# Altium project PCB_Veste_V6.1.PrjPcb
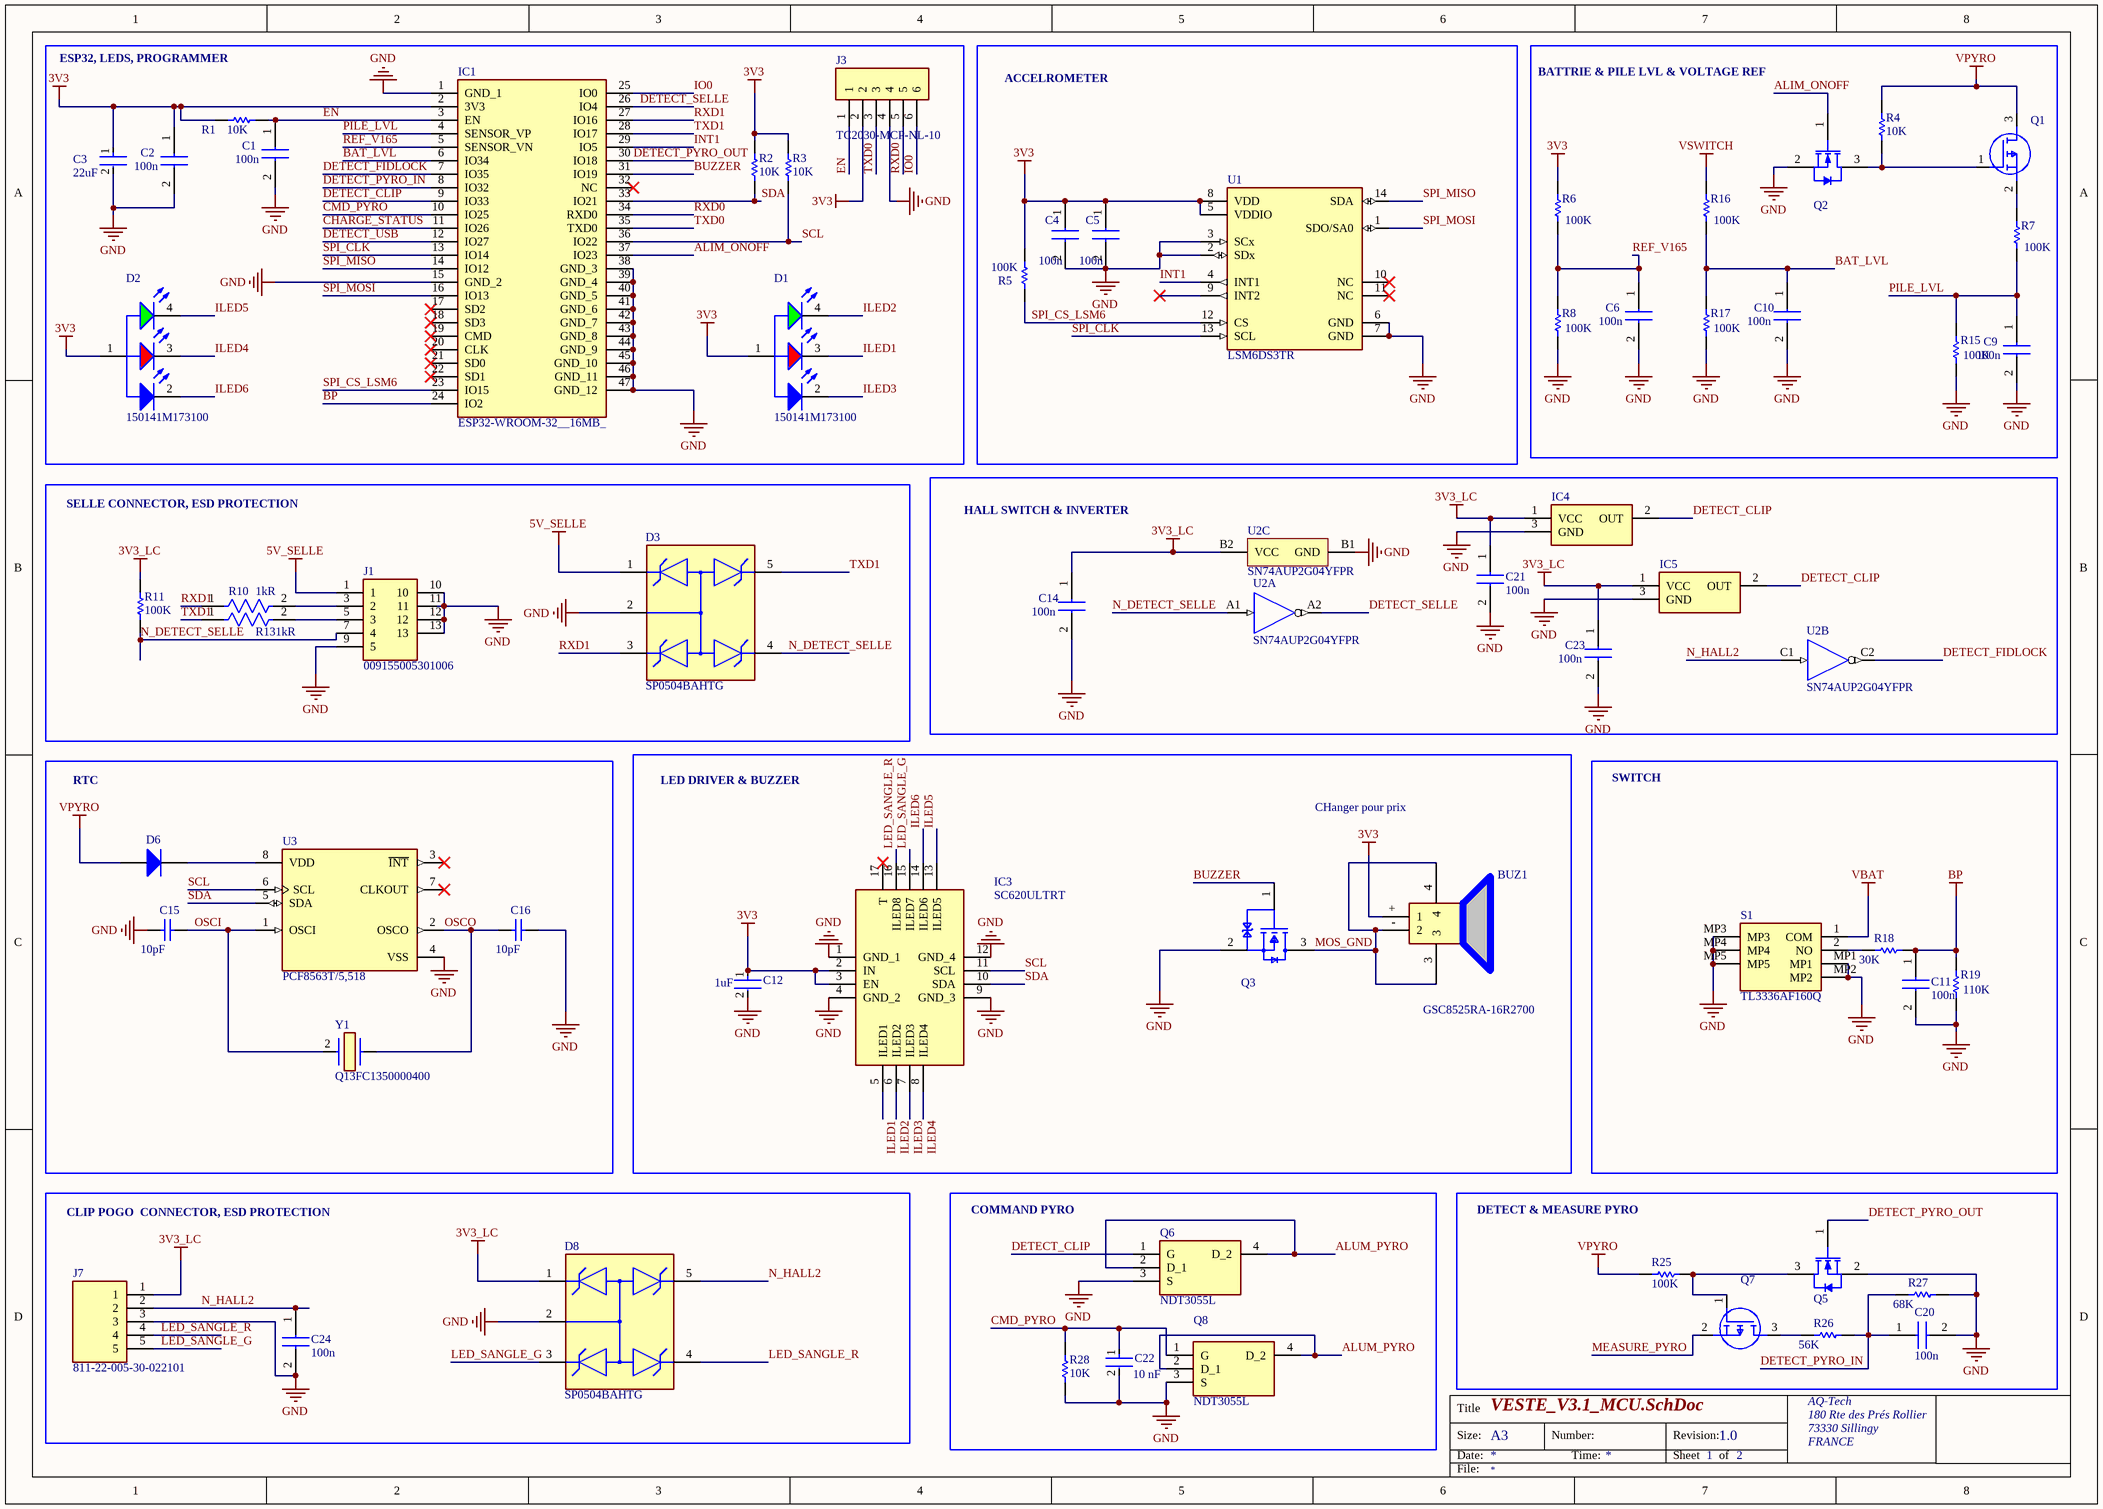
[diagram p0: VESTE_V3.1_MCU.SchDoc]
CAGE_CODE: ?????; CONTRACT_NUMBER: <CONTRACT NO>; DOC_NO_ASSY_DWG: <ASSY DWG NO>; DOC_NO_BOM: <BOM DOC NO>; DOC_NO_FAB_DWG: <FAB DWG NO>; DOC_NO_SCH_DWG: <SCH DWG NO>; PCB_2_DEC_TOL: +/-.01; PCB_3_DEC_TOL: +/-.010; PCB_ANG_TOL: +/-1/2; PCB_ASSEMBLY_NO: <PCB ASSY NO>; PCB_CHECKER: - -----; PCB_CHECKER_APP_DATE: --/--/----; PCB_DESIGNER: - -----; PCB_DESIGNER_APP_DATE: --/--/----; PCB_DWG_NO: <PCB DWG NO>; PCB_ENGINEER: - -----; PCB_ENGINEER_APP_DATE: --/--/----; PCB_PART_NUMBER: <PCB PN>; PCB_REV: A; SCH_REV: A
2 sheets, 108 parts. Net scope: global (net labels, ports and power ports of the same name join across sheets).
Board file: PCB_VESTE_6.1.PcbDoc
Sheets:
  VESTE_V3.1_MCU.SchDoc
  VESTE_V3.1_PSU.SchDoc

## Sheet VESTE_V3.1_MCU.SchDoc: DEV-09-17 MERE
size A3; ENG_APP_DATE: --/--/--; DSN_APP_DATE: --/--/--; CHK_APP_DATE: --/--/--; Date: 22/11/2017; Organization: Altium Limited; Address1: L3, 12a Rodborough Rd; Address2: Frenchs Forest; Address3: NSW; Address4: Australia 2086; Revision: 1.0; SheetNumber: 1; SheetTotal: 2; PageSetup: Record=PageOptions¦CenterHorizontal=True¦CenterVertical=True¦PrintScale=0.97¦XCorrection=1.00¦YCorrection=1.00¦PrintKind=0¦BorderSize=5000000¦LeftOffset=0¦BottomOffset=0¦Orientation=2¦PaperLength=1000¦PaperWidth=1000¦Scale=100¦PaperSource=7¦PrintQuality=-3¦MediaType=1¦DitherType=10¦PaperKind=A4¦PrintScaleMode=1

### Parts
BUZ1  GSC8525RA-16R2700  [BUZ-SMD_4P-L8.5-W8.5-P8.50-TL]
C1  Capacitance: 100n  [CAPC1608X90N]
C2  Capacitance: 100n  [CAPC1608X90N]
C3  Capacitance: 22uF  [FP-GRM188-0_2-IPC_C]  (hidden comment: GRM188R61A226ME15D)
C4  Capacitance: 100n  [CAPC1608X90N]
C5  Capacitance: 100n  [CAPC1608X90N]
C6  Capacitance: 100n  [CAPC1608X90N]
C9  Capacitance: 100n  [CAPC1608X90N]
C10  Capacitance: 100n  [CAPC1608X90N]
C11  Capacitance: 100n  [CAPC1608X90N]
C12  Capacitance: 1uF  [FP-CL511-IPC_C]  (hidden comment: CL05A105KP5NNNC)
C14  Capacitance: 100n  [CAPC1608X90N]
C15  Capacitance: 10pF  [CAPC1005X55X25ML05T05]  (hidden comment: CC0402JRNPO9BN100)
C16  Capacitance: 10pF  [CAPC1005X55X25ML05T05]  (hidden comment: CC0402JRNPO9BN100)
C20  Capacitance: 100n  [CAPC1608X90N]
C21  Capacitance: 100n  [CAPC1608X90N]
C22  value 10 nF  [FP-CC0402-MFG]  (hidden comment: CC0402KRX7R9BB103)
C23  Capacitance: 100n  [CAPC1608X90N]
C24  Capacitance: 100n  [CAPC1608X90N]
D1  150141M173100  [WL-SFTW_3528_150141M173100]
D2  150141M173100  [WL-SFTW_3528_150141M173100]
D3  SP0504BAHTG  [FP-SP0504BAHTG-MFG]
D6  1N4148WS-7-F  [DIOD-SOD323-2-A_V]  (value not drawn)
D8  SP0504BAHTG  [FP-SP0504BAHTG-MFG]
IC1  ESP32-WROOM-32__16MB_  [ESP32WROOM3216MB]
IC3  SC620ULTRT  [QFN50P300X300X60-17N]
IC4  TMAG5231A1CQDBZR  [SOT95P237X112-3N]  (value not drawn)
IC5  TMAG5231A1CQDBZR  [SOT95P237X112-3N]  (value not drawn)
J1  009155005301006  [009155005301006]
J3  TC2030-MCP-NL-10  [TC2030MCPNL10]
J7  811-22-005-30-022101  [8112200530022101]
Q1  DMP3125L-7  [SOT96P240X110-3N]  (value not drawn)
Q2  2N7002P,215  [NXP-SOT23_L]  (value not drawn)
Q3  DMN3730U-7  [FP-SOT23-MFG]  (value not drawn)
Q5  2N7002P,215  [NXP-SOT23_L]  (value not drawn)
Q6  NDT3055L  [SOT230P700X180-4N]
Q7  DMP3125L-7  [SOT96P240X110-3N]  (value not drawn)
Q8  NDT3055L  [SOT230P700X180-4N]
R1  Resistance: 10K  [RESC1005X40X25ML05T05]  (hidden comment: ERJ-2GEJ103X)
R2  Resistance: 10K  [RESC1005X40X25ML05T05]  (hidden comment: ERJ-2GEJ103X)
R3  Resistance: 10K  [RESC1005X40X25ML05T05]  (hidden comment: ERJ-2GEJ103X)
R4  Resistance: 10K  [RESC1005X40X25ML05T05]  (hidden comment: ERJ-2GEJ103X)
R5  Resistance: 100K  [RESC1005X40X25NL05T10]  (hidden comment: RC0402FR-07100KL)
R6  Resistance: 100K  [RESC1005X40X25NL05T10]  (hidden comment: RC0402FR-07100KL)
R7  Resistance: 100K  [RESC1005X40X25NL05T10]  (hidden comment: RC0402FR-07100KL)
R8  Resistance: 100K  [RESC1005X40X25NL05T10]  (hidden comment: RC0402FR-07100KL)
R10  Resistance: 1kR  [FP-RC0603-0_55-IPC_C]  (hidden comment: RC0603FR-071KL)
R11  Resistance: 100K  [RESC1005X40X25NL05T10]  (hidden comment: RC0402FR-07100KL)
R13  Resistance: 1kR  [FP-RC0603-0_55-IPC_C]  (hidden comment: RC0603FR-071KL)
R15  Resistance: 100K  [RESC1005X40X25NL05T10]  (hidden comment: RC0402FR-07100KL)
R16  Resistance: 100K  [RESC1005X40X25NL05T10]  (hidden comment: RC0402FR-07100KL)
R17  Resistance: 100K  [RESC1005X40X25NL05T10]  (hidden comment: RC0402FR-07100KL)
R18  Resistance: 30K  [RESC1005X40X25LL05T10]  (hidden comment: RC0402FR-0730KL)
R19  Resistance: 110K  [RESC1005X40X25LL05T10]  (hidden comment: RC0402FR-07110KL)
R25  Resistance: 100K  [RESC1005X40X25NL05T10]  (hidden comment: RC0402FR-07100KL)
R26  Resistance: 56K  [RESC1005X40X25ML05T10]  (hidden comment: RC0402FR-0756KL)
R27  Resistance: 68K  [RESC1005X40X25ML05T10]  (hidden comment: RC0402FR-0768KL)
R28  Resistance: 10K  [RESC1005X40X25ML05T05]  (hidden comment: ERJ-2GEJ103X)
S1  TL3336AF160Q  [TL3336AF160Q]
U1  LSM6DS3TR  [FP-LGA-14-DM00249496-MFG]
U2  SN74AUP2G04YFPR  [YFF0006AAAA]  (parts A,B,C of 3)
U3  PCF8563T/5,518  [FP-SOT96-1-MFG]
Y1  Q13FC1350000400  [Q13FC1350000400]

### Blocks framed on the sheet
ESP32, LEDS, PROGRAMMER: C1-C3 D1 D2 IC1 J3 R1-R3
ACCELROMETER: C4 C5 R5 U1
BATTRIE & PILE LVL & VOLTAGE REF: C6 C9 C10 Q1 Q2 R4 R6-R8 R15-R17
SELLE CONNECTOR, ESD PROTECTION: D3 J1 R10 R11 R13
HALL SWITCH & INVERTER: C14 C21 C23 IC4 IC5 U2
RTC: C15 C16 D6 U3 Y1
SWITCH: C11 R18 R19 S1
CLIP POGO  CONNECTOR, ESD PROTECTION: C24 D8 J7
COMMAND PYRO: C22 Q6 Q8 R28
DETECT & MEASURE PYRO: C20 Q5 Q7 R25-R27

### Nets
3V3: BUZ1.+(1) C2.1 C3.1 C4.1 C5.1 C12.1 D1.1(A) D2.1(A) IC1.2(3V3) IC3.2(IN) IC3.3(EN) J3.2 R1.2 R2.1 R3.1 R5.2 R6.2 U1.5(VDDIO) U1.8(VDD)
3V3_LC: C14.1 C21.1 C23.1 D8.1 IC4.1(VCC) IC5.1(VCC) J7.1 R11.1 U2.B2(VCC)
5V_SELLE: D3.1 J1.1
BP: C11.1 IC1.24(IO2) R18.2 R19.2
GND: C1.2 C2.2 C3.2 C4.2 C5.2 C6.2 C9.2 C10.2 C11.2 C12.2 C14.2 C15.1 C16.1 C20.2 C21.2 C22.2 C23.2 C24.2 D3.2 D8.2 IC1.1(GND_1) IC1.15(GND_2) IC1.38(GND_3) IC1.39(GND_4) IC1.40(GND_5) IC1.41(GND_6) IC1.42(GND_7) IC1.43(GND_8) IC1.44(GND_9) IC1.45(GND_10) IC1.46(GND_11) IC1.47(GND_12) IC3.1(GND_1) IC3.4(GND_2) IC3.9(GND_3) IC3.12(GND_4) IC4.3(GND) IC5.3(GND) J1.9(5) J1.10 J1.11 J1.12 J1.13 J3.4 J7.3 Q2.2(S) Q3.2(S) Q5.2(S) Q6.3(S) Q8.3(S) R8.1 R15.1 R17.1 R19.1 R27.2 R28.1 S1.MP1 S1.MP2 S1.MP3 S1.MP4 S1.MP5 U1.2(SDx) U1.3(SCx) U1.6(GND) U1.7(GND) U2.B1(GND) U3.4(VSS)
VBAT: S1.1(COM)
VPYRO: D6.1(A) Q1.3(D) R4.1 R25.2
VSWITCH: R16.2
ALIM_ONOFF: IC1.37(IO23) Q2.1(G)
ALUM_PYRO: Q6.2(D_1) Q6.4(D_2) Q7.2(S) Q8.2(D_1) Q8.4(D_2)  [also labelled MEASURE_PYRO]
BAT_LVL: C10.1 IC1.6(IO34) R16.1 R17.2
BUZZER: IC1.31(IO19) Q3.1(G)
CHARGE_STATUS: IC1.11(IO26)
CMD_PYRO: C22.1 IC1.10(IO25) Q8.1(G) R28.2
DETECT_CLIP: IC1.9(IO33) IC4.2(OUT) IC5.2(OUT) Q6.1(G)
DETECT_FIDLOCK: IC1.7(IO35) U2.C2(2Y)
DETECT_PYRO_IN: C20.1 IC1.8(IO32) R26.2 R27.1
DETECT_PYRO_OUT: IC1.30(IO18) Q5.1(G)
DETECT_SELLE: IC1.26(IO4) U2.A2(1Y)
DETECT_USB: IC1.12(IO27)
EN: C1.1 IC1.3(EN) J3.1 R1.1
ILED1: D1.3(K) IC3.5(ILED1)
ILED2: D1.4(K) IC3.6(ILED2)
ILED3: D1.2(K) IC3.7(ILED3)
ILED4: D2.3(K) IC3.8(ILED4)
ILED5: D2.4(K) IC3.13(ILED5)
ILED6: D2.2(K) IC3.14(ILED6)
INT1: IC1.29(IO5) U1.4(INT1)
IO0: IC1.25(IO0) J3.6
LED_SANGLE_G: D8.3 IC3.15(ILED7) J7.5
LED_SANGLE_R: D8.4 IC3.16(ILED8) J7.4
MOS_GND: BUZ1.3 BUZ1.4 BUZ1.-(2) Q3.3(D)
N_DETECT_SELLE: D3.4 J1.7(4) R11.2 U2.A1(1A)
N_HALL2: C24.1 D8.5 J7.2 U2.C1(2A)
OSCI: C15.2 U3.1(OSCI) Y1.2(CRYSTAL_2)
OSCO: C16.2 U3.2(OSCO) Y1.?1
PILE_LVL: C9.1 IC1.4(SENSOR_VP) R7.1 R15.2
REF_V165: C6.1 IC1.5(SENSOR_VN) R6.1 R8.2
RXD0: IC1.34(RXD0) J3.5
RXD1: D3.3 IC1.27(IO16) R10.1
SCL: IC1.36(IO22) IC3.11(SCL) R3.2 U3.6(SCL)
SDA: IC1.33(IO21) IC3.10(SDA) R2.2 U3.5(SDA)
SPI_CLK: IC1.13(IO14) U1.13(SCL)
SPI_CS_LSM6: IC1.23(IO15) R5.1 U1.12(CS)
SPI_MISO: IC1.14(IO12) U1.14(SDA)
SPI_MOSI: IC1.16(IO13) U1.1(SDO/SA0)
TXD0: IC1.35(TXD0) J3.3
TXD1: D3.5 IC1.28(IO17) R13.1
NetD6_2: D6.2(K) U3.8(VDD)
NetJ1_3: J1.3(2) R10.2
NetJ1_5: J1.5(3) R13.2
NetQ1_1: Q1.1(G) Q2.3(D) R4.2
NetQ1_2: Q1.2(S) R7.2
NetQ5_3: Q5.3(D) Q7.1(G) R25.1
NetQ7_3: Q7.3(D) R26.1
NetR18_1: R18.1 S1.2(NO)

Not connected (* = marked no-connect by the designer): IC1 17(SD2)* 18(SD3)* 19(CMD)* 20(CLK)* 21(SD0)* 22(SD1)* 32(NC)*; IC3 17(T)*; U1 9(INT2)* 10(NC)* 11(NC)*; U3 3(~{INT})* 7(CLKOUT)*

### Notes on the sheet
- LED DRIVER & BUZZER
- CHanger pour prix

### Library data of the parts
BUZ1 = GSC8525RA-16R2700: Externally Driven 88dB@3V,10cm Magnetic 3V 2.67kHz Plugin,L=8.5mm Buzzers ROHS
C1 C2 C4-C6 C9-C11 C14 C20 C21 C23 C24 = CL10B104KB8NNNC: Capacitor; Manufacturer_Name: SAMSUNG
C3 = CMP-2000-06337-3: Chip Multilayer Ceramic Capacitors for General Purpose, 0603, 22uF, X5R, 15%, 20%, 10V
C12 = CMP-13271-001936-1: Cap Ceramic 1uF 10V X5R ±10% SMD 0402 +85°C Paper T/R
C15 C16 = CMP-2100-03589-1: Chip Capacitor, 10 pF, +/- 5%, 50 V, -55 to 125 degC, 0402 (1005 Metric), RoHS, Tape and Reel; Manufacturer: Yageo; Insulation Resistance: 100GR; Voltage Rating (DC): 50V; Dielectric Material: Ceramic; Temperature Coefficient: 30ppm/degC; Dielectric: C0G
C22 = CMP-2100-03592-2: CAP CER 10000PF 50V X7R 0402; Manufacturer: YAGEO; Temperature Coefficient: 30ppm/°C; Material: Ceramic; Automotive Grade: NA; Tolerance: 0.1
D1 D2 = CMP-1431-00001-2: NexarPartId: 29717795; Forward Current: 100mA; Peak Wavelength: 465nm; Viewing Angle: 120°; Color: Green, Red; Max Reverse Voltage (DC): 5V; Forward Voltage: 3.2V; Dominant Wavelength: 520nm; Test Current: 20mA; Power Dissipation: 72mW; Wavelength: 470nm; Lens Style: Clear, Round; Luminous Intensity: 230mcd
D3 D8 = CMP-08607-000010-1: TVS DIODE 5.5V 8.5V SOT23-5; Manufacturer: Littelfuse; Direction: Unidirectional; Number Of Channels: 4; Value: 30pF; Standoff Height: 0mm
D6 = CMP-1667-00004-1: Fast Switching Diode, 75 V, 0.3 A, -65 to 150 degC, 2-Pin SOD323, RoHS, Tape and Reel
IC1 = ESP32-WROOM-32__16MB_: Integrated Circuit; Manufacturer_Name: Espressif Systems; Manufacturer_Part_Number: ESP32-WROOM-32 (16MB)
IC3 = SC620ULTRT: Integrated Circuit; Manufacturer_Name: SEMTECH
IC4 IC5 = TMAG5231A1CQDBZR: Integrated Circuit; Manufacturer_Name: Texas Instruments
J1 = 009155005301006: Connector; Manufacturer_Name: AVX; Manufacturer_Part_Number: 009155003301006
J3 = TC2030-MCP-NL-10: Connector; Manufacturer_Name: Tag Connect
J7 = 811-22-005-30-022101: Connector 5 pin Height  5,512 mm; Manufacturer_Name: Mill-Max
Q1 Q7 = DMP3125L-7: MOSFET (P-Channel); Manufacturer_Name: Diodes Inc.
Q2 Q5 = CMP-1259-00082-1: N-Channel Trench MOSFET, 60 V, 0.36 A, -55 to 150 degC, 3-Pin SOT23, Tape and Reel; Manufacturer: NXP Semiconductors; Channel Type: N; Automotive Qualified: Y; VDS [max] (V): 60; Packing: Tape & Reel; ID [max] (A): 0.36; VGSth [typ] (V): 1.75; IDM [max] (A): 1.2
Q3 = CMP-12801-000041-1: MOSFET N-CH 30V 750MA SOT23; Manufacturer: Diodes Inc.; Number Of N Channels: 1; Threshold Vgs Max: 0.95V; Max Junction Temp: +150°C; Automotive Grade: Grade 0; Gate To Source Voltage: 8V; Power Dissipation: 0.45W; Gate Charge At Vgs: 1.6nC @ 4.5V; Turn Off Delay Time: 38ns; Depletion Mode: False; Typ Forward Diode Voltage: 0.7V; Rthja Max: 275°C/W; Turn On Delay Time: 3.5ns; Drain To Source Resistance: 460mΩ; Pulse Drain Current: 10A; Threshold Vgs Min: 0.45V; Continuous Drain Current: 0.75A; Max Forward Diode Voltage: 1.2V; Standoff Height: 0.013mm; Input Capacitace At Vds: 64.3pF @ 25V
Q6 Q8 = NDT3055L: Transistor; Manufacturer_Name: onsemi
R1-R4 R28 = CMP-2002-00433-1: Manufacturer: Panasonic
R5-R8 R11 R15-R17 R25 = CMP-2002-07343-1: Manufacturer: Yageo / Phycomp
R10 R13 = CMP-1659-00009-5: RES 1K OHM 1% 1/10W 0603; Voltage Rating: 50V; Power Rating: 100mW; Temperature Coefficient: 100ppm/°C
R18 = CMP-2002-07602-1: Manufacturer: Yageo / Phycomp
R19 = CMP-2002-07022-1: Manufacturer: Yageo / Phycomp
R26 = CMP-1011-00708-2: Manufacturer: Yageo / Phycomp
R27 = CMP-1011-00717-2: Manufacturer: Yageo / Phycomp
S1 = TL3336AF160Q: Switch; Manufacturer_Name: E-Switch
U1 = CMP-2000-05193-2: IMU ACCEL/GYRO I2C/SPI 14VFLGA; Manufacturer: STMicroelectronics; Sensor Type: Temperature,Accelerometer,Gyroscope; Gyro Range: 125/250/500/1000/2000°/s; Min Supply Voltage: 1.62V; Operating Supply Current: 9-900uA; Accel Range: 2/4/8/16g; Max Supply Voltage: 3.6V; Sensor Output: I2C,SPI
U2 = CMP-0859-01053-4: Low-Power Dual Inverter Gate, YFP0006AAAA, LARGE T&R; Manufacturer: Texas Instruments; Logic: Inverting; Voltage(Nom)(V): 0.8,1.2,1.5,1.8,2.5,3.3; ICC @ Nom Voltage(Max)(mA): 0.0009; VCC(Max)(V): 3.6; Output Drive (IOL/IOH)(Max)(mA): 20/-20; tpd @ Nom Voltage(Max)(ns): 32.8,20.9,14.2,11,7.6,6.2; Input Type: CMOS; Schmitt Trigger: No; VCC(Min)(V): 0.8; Sub-Family: Inverting Buffer/Driver; Technology Family: AUP; Bits(#): 2; F @ Nom Voltage(Max)(Mhz): 100; Rating: Catalog
U3 = CMP-10083-000010-1: IC RTC CLK/CALENDAR I2C 8-SOIC; Manufacturer: NXP; Nominal Supply Current: 0.225-0.95uA; Interface: I2C,2-Wire; Min Supply Voltage: 1V; Frequency: 400kHz; Standoff Height: 0.1mm; Number Of Outputs: 1; Max Supply Voltage: 5.5V
Y1 = Q13FC1350000400: Crystal or Oscillator; Manufacturer_Name: Seiko Epson Corporation

## Sheet VESTE_V3.1_PSU.SchDoc: DEV-09-17 MERE
size A3; Date: 22/11/2017; Organization: Altium Limited; Address1: L3, 12a Rodborough Rd; Address2: Frenchs Forest; Address3: NSW; Address4: Australia 2086; Revision: 1.0; SheetNumber: 2; SheetTotal: 2; PageSetup: Record=PageOptions¦CenterHorizontal=True¦CenterVertical=True¦PrintScale=0.97¦XCorrection=1.00¦YCorrection=1.00¦PrintKind=0¦BorderSize=5000000¦LeftOffset=0¦BottomOffset=0¦Orientation=2¦PaperLength=1000¦PaperWidth=1000¦Scale=100¦PaperSource=7¦PrintQuality=-3¦MediaType=1¦DitherType=10¦PaperKind=A4¦PrintScaleMode=1
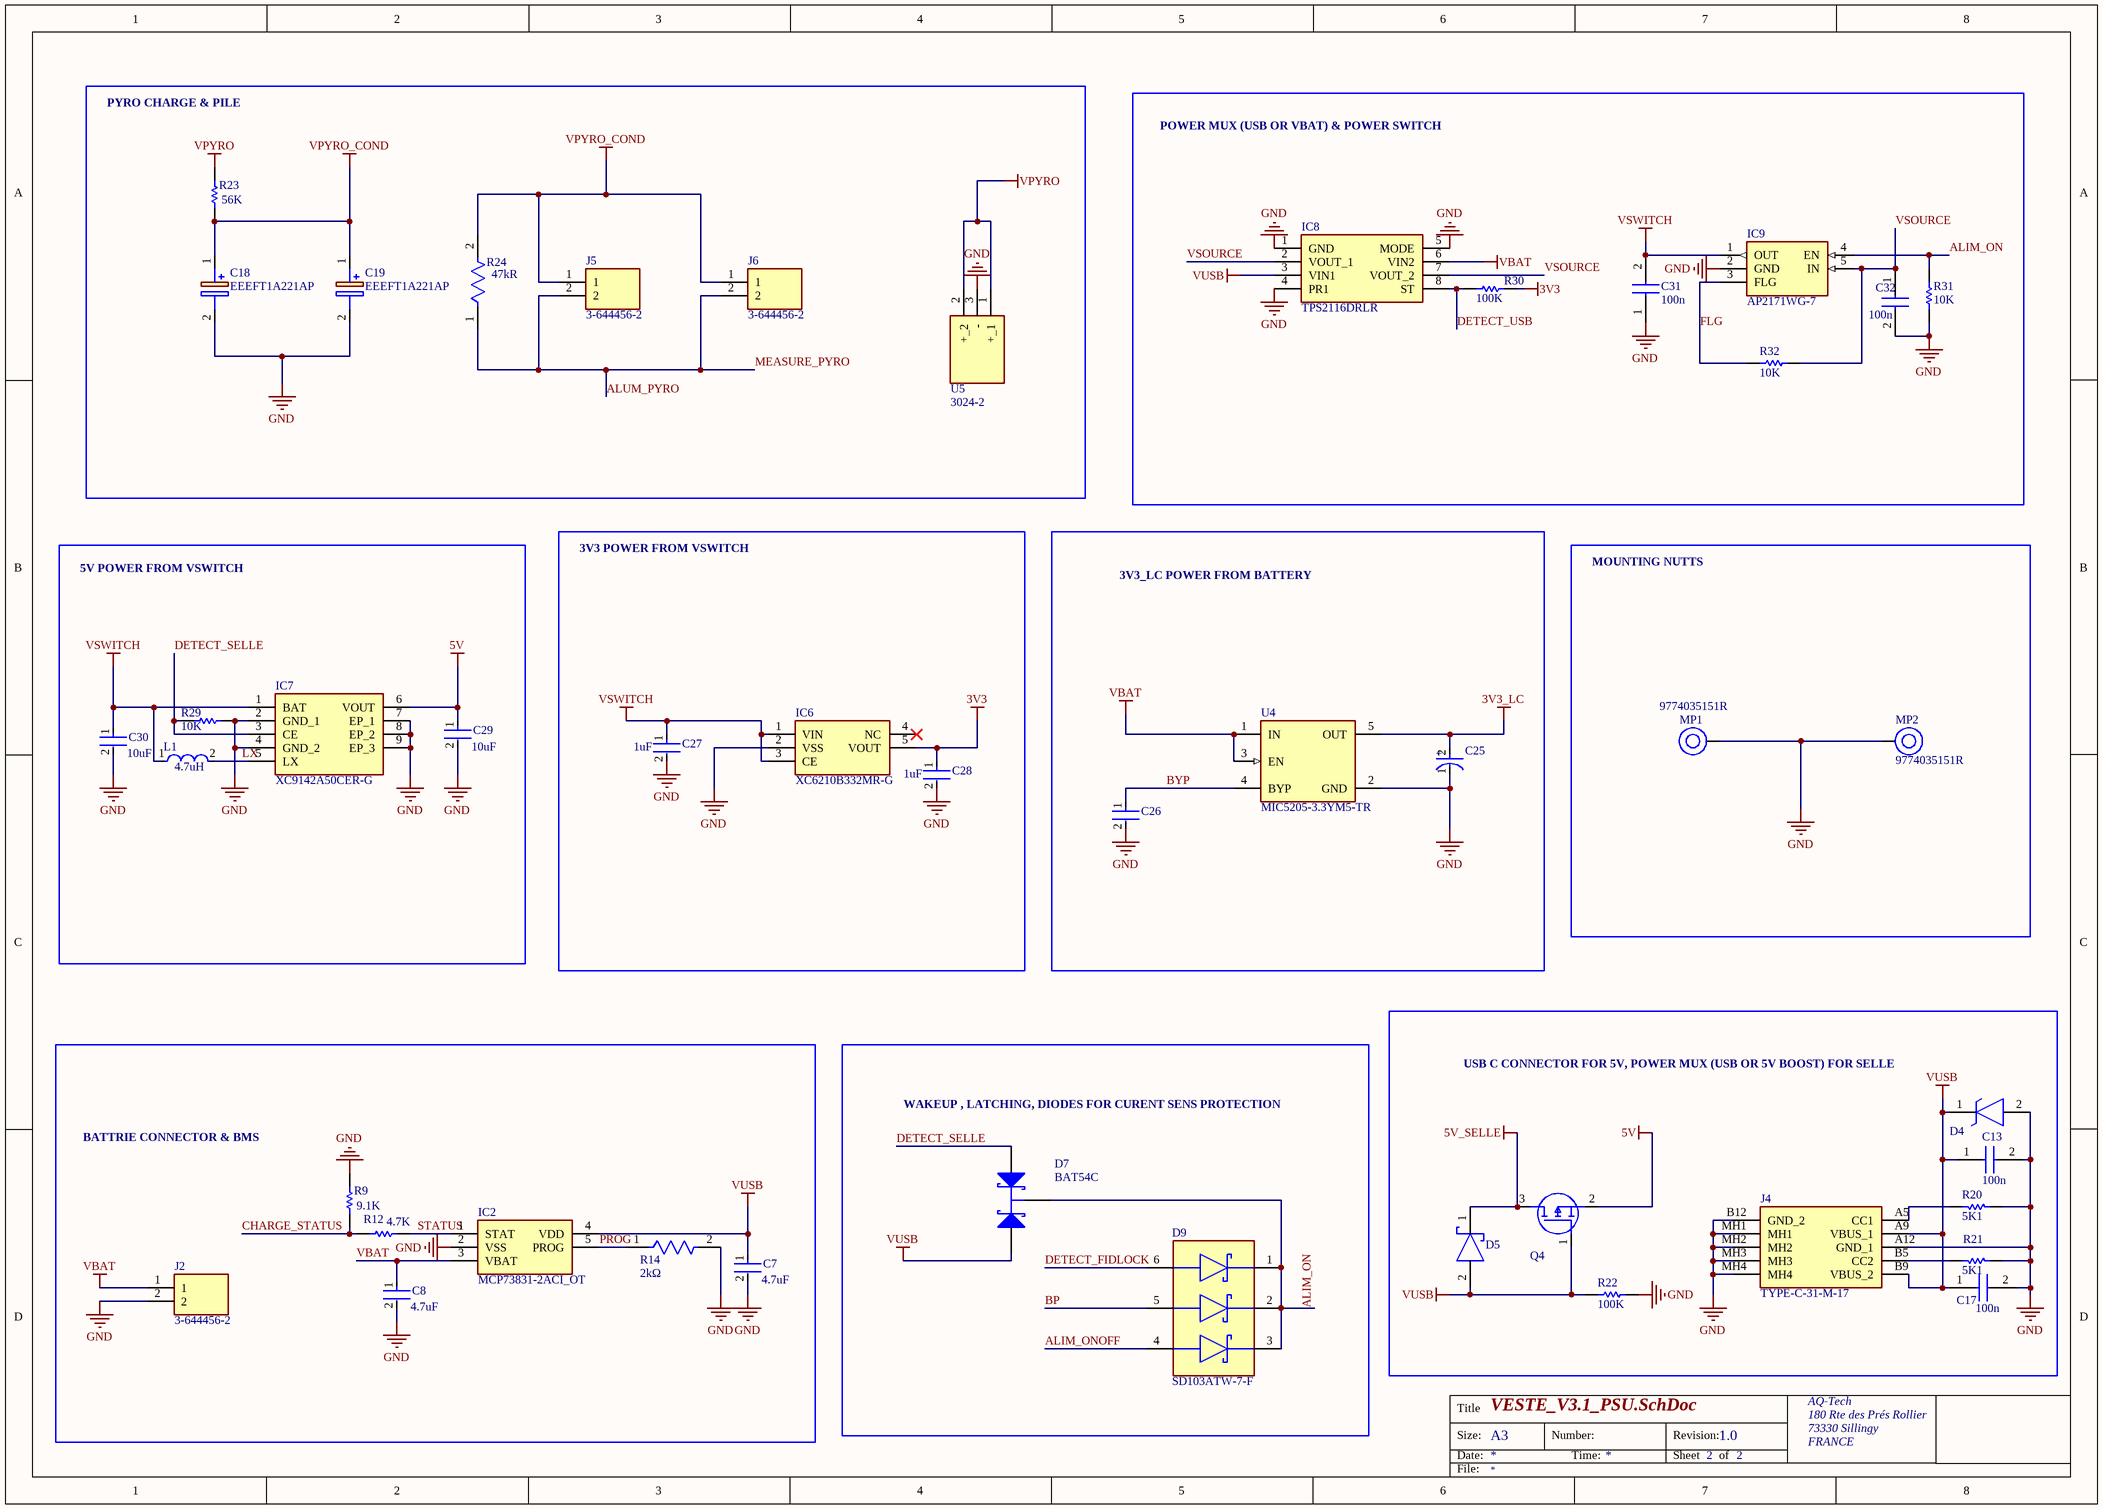
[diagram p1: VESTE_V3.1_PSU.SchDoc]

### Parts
C7  Capacitance: 4.7uF  [FP-CL828-IPC_C]  (hidden comment: CL05A475KP5NRNC)
C8  Capacitance: 4.7uF  [FP-CL828-IPC_C]  (hidden comment: CL05A475KP5NRNC)
C13  Capacitance: 100n  [CAPC1608X90N]
C17  Capacitance: 100n  [CAPC1608X90N]
C18  EEEFT1A221AP  [EEE1AA101SP]
C19  EEEFT1A221AP  [EEE1AA101SP]
C25  TAJA225K016RNJ  [FP-TAJA-MFG]  (value not drawn)
C26  CL05B471KB5NNNC  [FP-CL23-IPC_C]  (value not drawn)
C27  Capacitance: 1uF  [FP-CL511-IPC_C]  (hidden comment: CL05A105KP5NNNC)
C28  Capacitance: 1uF  [FP-CL511-IPC_C]  (hidden comment: CL05A105KP5NNNC)
C29  Capacitance: 10uF  [FP-CL05A106MP5NUNC-MFG]  (hidden comment: CL05A106MP5NUNC)
C30  Capacitance: 10uF  [FP-CL05A106MP5NUNC-MFG]  (hidden comment: CL05A106MP5NUNC)
C31  Capacitance: 100n  [CAPC1608X90N]
C32  Capacitance: 100n  [CAPC1608X90N]
D4  D5V0M1U2S9Q-7  [SODFL1006X40N]  (value not drawn)
D5  RB168MM100TR  [FP-PMDU-MFG]  (value not drawn)
D7  BAT54C  [NXP-SOT23-3_V]
D9  SD103ATW-7-F  [FP-SOT363-IPC_A]
IC2  MCP73831-2ACI_OT  [SOT95P270X145-5N]
IC6  XC6210B332MR-G  [SOT95P280X130-5N]
IC7  XC9142A50CER-G  [XC9142A50CERG]
IC8  TPS2116DRLR  [SOTFL50P160X60-8N]
IC9  AP2171WG-7  [SOT95P282X130-5N]
J2  3-644456-2  [HDRV2W67P0X254_1X2_478X234X1029P]
J4  TYPE-C-31-M-17  [TYPEC31M17]
J5  3-644456-2  [HDRV2W67P0X254_1X2_478X234X1029P]
J6  3-644456-2  [HDRV2W67P0X254_1X2_478X234X1029P]
L1  Inductance: 4.7uH  [FP-LQH5BPB_T0-MFG]  (hidden comment: LQH5BPN4R7NT0L)
MP1  9774035151R  [9774035151]
MP2  9774035151R  [9774035151]
Q4  DMP3125L-7  [SOT96P240X110-3N]  (value not drawn)
R9  Resistance: 9.1K  [RESC1005X40X25NL05T10]  (hidden comment: RC0402FR-079K1L)
R12  Resistance: 4.7K  [RESC1005X40X25NL05T10]  (hidden comment: RC0402FR-074K7L)
R14  Resistance: 2kΩ  [FP-RC_L0402-MFG]  (hidden comment: RC0402FR-072KL)
R20  Resistance: 5K1  [RESC1005X40X25NL05T10]  (hidden comment: RC0402FR-075K1L)
R21  Resistance: 5K1  [RESC1005X40X25NL05T10]  (hidden comment: RC0402FR-075K1L)
R22  Resistance: 100K  [RESC1005X40X25NL05T10]  (hidden comment: RC0402FR-07100KL)
R23  Resistance: 56K  [RESC1005X40X25ML05T10]  (hidden comment: RC0402FR-0756KL)
R24  Resistance: 47kR  [FP-RC0603FR-0747KL-MFG]  (hidden comment: RC0603FR-0747KL)
R29  Resistance: 10K  [RESC1005X40X25ML05T05]  (hidden comment: ERJ-2GEJ103X)
R30  Resistance: 100K  [RESC1005X40X25NL05T10]  (hidden comment: RC0402FR-07100KL)
R31  Resistance: 10K  [RESC1005X40X25ML05T05]  (hidden comment: ERJ-2GEJ103X)
R32  Resistance: 10K  [RESC1005X40X25ML05T05]  (hidden comment: ERJ-2GEJ103X)
U4  MIC5205-3.3YM5-TR  [FP-M5-MFG]
U5  3024-2  [30242]

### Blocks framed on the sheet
PYRO CHARGE & PILE: C18 C19 J5 J6 R23 R24 U5
POWER MUX (USB OR VBAT) & POWER SWITCH: C31 C32 IC8 IC9 R30-R32
5V POWER FROM VSWITCH: C29 C30 IC7 L1 R29
3V3 POWER FROM VSWITCH: C27 C28 IC6
3V3_LC POWER FROM BATTERY: C25 C26 U4
MOUNTING NUTTS: MP1 MP2
BATTRIE CONNECTOR & BMS: C7 C8 IC2 J2 R9 R12 R14
WAKEUP , LATCHING, DIODES FOR CURENT SENS PROTECTION: D7 D9

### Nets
3V3: C28.1 IC6.5(VOUT) R30.1
3V3_LC: C25.2(A) U4.5(OUT)
5V: C29.1 IC7.6(VOUT) Q4.2(S)
5V_SELLE: D5.1(C) Q4.3(D)
BP: D9.5(2_ANODE)
GND: C7.2 C8.2 C13.2 C17.2 C18.2(-) C19.2(-) C25.1(C) C26.2 C27.2 C28.2 C29.2 C30.2 C31.1 C32.2 D4.2(A) IC2.2(VSS) IC6.2(VSS) IC7.2(GND_1) IC7.4(GND_2) IC7.7(EP_1) IC7.8(EP_2) IC7.9(EP_3) IC8.1(GND) IC8.4(PR1) IC8.5(MODE) IC9.2(GND) J2.2 J4.A12(GND_1) J4.B12(GND_2) J4.MH1 J4.MH2 J4.MH3 J4.MH4 MP1.1 MP2.1 R9.2 R14.2 R20.1 R21.1 R22.1 R29.2 R31.2 U4.2(GND) U5.3(-)
VBAT: C8.1 IC2.3(VBAT) IC8.6(VIN2) J2.1 U4.1(IN) U4.3(EN)
VPYRO: R23.2 U5.1(+_1) U5.2(+_2)
VPYRO_COND: C18.1(+) C19.1(+) J5.1 J6.1 R23.1 R24.2
VSWITCH: C27.1 C30.1 C31.2 IC6.1(VIN) IC6.3(CE) IC7.1(BAT) IC9.1(OUT) L1.1
VUSB: C7.1 C13.1 C17.1 D4.1(K) D5.2(A) D7.2(A) IC2.4(VDD) IC8.3(VIN1) J4.A9(VBUS_1) J4.B9(VBUS_2) Q4.1(G) R22.2
ALIM_ON: D7.3(K) D9.1(1_CATHODE) D9.2(2_CATHODE) D9.3(3_CATHODE) IC9.4(EN) R31.1
ALIM_ONOFF: D9.4(3_ANODE)
ALUM_PYRO: J5.2 J6.2 R24.1  [also labelled MEASURE_PYRO]
BYP: C26.1 U4.4(BYP)
CHARGE_STATUS: R9.1 R12.1
DETECT_FIDLOCK: D9.6(1_ANODE)
DETECT_SELLE: D7.1(A) IC7.3(CE) R29.1
DETECT_USB: IC8.8(ST) R30.2
FLG: IC9.3(FLG) R32.1
LX: IC7.5(LX) L1.2
PROG: IC2.5(PROG) R14.1
STATUS: IC2.1(STAT) R12.2
VSOURCE: C32.1 IC8.2(VOUT_1) IC8.7(VOUT_2) IC9.5(IN) R32.2
NetJ4_A5: J4.A5(CC1) R20.2
NetJ4_B5: J4.B5(CC2) R21.2

Not connected (* = marked no-connect by the designer): IC6 4(NC)*

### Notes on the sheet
- USB C CONNECTOR FOR 5V, POWER MUX (USB OR 5V BOOST) FOR SELLE

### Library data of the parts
C7 C8 = CMP-13271-001251-1: Cap Ceramic 4.7uF 10V X5R ±10% SMD 0402 +85°C Paper T/R
C13 C17 C31 C32 = CL10B104KB8NNNC: Capacitor; Manufacturer_Name: SAMSUNG
C18 C19 = EEEFT1A221AP: Capacitor Polarised; Manufacturer_Name: Panasonic
C25 = CMP-04424-000432-1: 2.2uF 16V  ±10% 6.5Ω 1206  SMD Tantalum Capacitor; Polarity: Polar; Leakage Current: 500nA; Dissipation Factor: 6%; ESR (Equivalent Series Resistance): 6.5R; Q Factor: 6
C26 = CMP-13271-000495-1: Cap Ceramic 470pF 50V X7R ±10% SMD 0402 +125°C Paper T/R
C27 C28 = CMP-13271-001936-1: as C12 on sheet VESTE_V3.1_MCU
C29 C30 = CMP-13271-000002-1: CAP CER 10UF 10V X5R 0402; Manufacturer: Samsung; Temperature Coefficient: 15%; Tolerance: 20%; Material: Ceramic
D4 = D5V0M1U2S9Q-7: TVS Diode (Uni-directional); Manufacturer_Name: Diodes Inc.
D5 = CMP-08971-000001-1: DIODE SCHOTTKY 100V 1A SOD123FL; Manufacturer: ROHM Semiconductor; Max Surge Forward Current: 40A; Max Junction Temp: +150°C; Peak Reverse Current: 0.4uA
D7 = CMP-0417-00003-1: Schottky Barrier Diode, 30 V, 2 uA, -55 to 150 degC, 3-Pin SOT23, RoHS, Tape and Reel; Manufacturer: NXP Semiconductors; IR (uA): 2; VF (mV): 800; Trr (ns): 5; Cd (pF): 10; VR (V): 30; Rth(j-a) (K/W): 500
D9 = CMP-12790-000076-1: DIODE ARRAY SCHOTTKY 40V SOT363; Current Rating: 350mA; Forward Voltage: 500mV; Peak Non-Repetitive Surge Current: 1A; Peak Reverse Current: 5uA; Power Rating: 200mW; Reverse Recovery Time: 10ns; Capacitance: 50pF; Average Rectified Current: 175mA
IC2 = MCP73831-2ACI_OT: Integrated Circuit; Manufacturer_Name: Microchip; Manufacturer_Part_Number: MCP73831-2ACI/OT
IC6 = XC6210B332MR-G: Integrated Circuit; Manufacturer_Name: Torex
IC7 = XC9142A50CER-G: Integrated Circuit; Manufacturer_Name: Torex
IC8 = TPS2116DRLR: Integrated Circuit; Manufacturer_Name: Texas Instruments
IC9 = AP2171WG-7: Integrated Circuit; Manufacturer_Name: Diodes Inc.
J2 J5 J6 = 3-644456-2: Connector; Manufacturer_Name: TE Connectivity
J4 = TYPE-C-31-M-17: Connector; Manufacturer_Name: Korean Hroparts Elec
L1 = CMP-06042-004027-1: Wire Wound Ferrite Inductor for Power Lines 4.7μH ±30% 0.0696Ω 2.0A 2020; Shielding: Shielded; DC Resistance (DCR): 58mR; Current Rating: 2A; Max DC Current: 3A; Test Frequency: 100kHz; Self Resonant Frequency: 40MHz
MP1 MP2 = CMP-03913-118307956-1: 9774035151R WA-SMSI SMT Steel Spacer, M2.5 Internal non Stop
Q4 = DMP3125L-7: as Q1 on sheet VESTE_V3.1_MCU
R9 = CMP-2002-07017-1: Manufacturer: Yageo / Phycomp
R12 = CMP-1011-00586-2: Manufacturer: Yageo / Phycomp
R14 = CMP-2002-07580-2: RES SMD 2K OHM 1% 1/16W 0402; Manufacturer: Yageo; Voltage Rating: 50V; Temperature Coefficient: 100ppm/°C; Power Rating: 0.0625W; Standoff Height: 0mm; Value: 2kΩ
R20 R21 = CMP-2002-07753-1: Manufacturer: Yageo / Phycomp
R22 R30 = CMP-2002-07343-1: Manufacturer: Yageo / Phycomp
R23 = CMP-1011-00708-2: Manufacturer: Yageo / Phycomp
R24 = CMP-1659-00055-2: RES SMD 47K OHM 1% 1/10W 0603; Voltage Rating: 50V; Temperature Coefficient: 100ppm/°C; Max Power Dissipation: 100mW
R29 R31 R32 = CMP-2002-00433-1: Manufacturer: Panasonic
U4 = CMP-06324-000014-1: IC REG LINEAR 3.3V 150MA SOT23-5; Manufacturer: Microchip; Number Of Outputs: 1; Output Type: Fixed; Min Supply Voltage: 2.5V; Accuracy Percentage: 2%; Dropout Voltage: 165mV; Max Supply Voltage: 16V; Max Junction Temp: +125°C; Standoff Height: 0mm
U5 = 3024-2: Undefined or Miscellaneous; Manufacturer_Name: Keystone Electronics

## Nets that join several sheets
3V3: VESTE_V3.1_MCU (19 pins), VESTE_V3.1_PSU (C28.1 IC6.5 R30.1)
3V3_LC: VESTE_V3.1_MCU (9 pins), VESTE_V3.1_PSU (C25.2 U4.5)
5V_SELLE: VESTE_V3.1_MCU (D3.1 J1.1), VESTE_V3.1_PSU (D5.1 Q4.3)
BP: VESTE_V3.1_MCU (C11.1 IC1.24 R18.2 R19.2), VESTE_V3.1_PSU (D9.5)
GND: VESTE_V3.1_MCU (67 pins), VESTE_V3.1_PSU (44 pins)
VBAT: VESTE_V3.1_MCU (S1.1), VESTE_V3.1_PSU (6 pins)
VPYRO: VESTE_V3.1_MCU (D6.1 Q1.3 R4.1 R25.2), VESTE_V3.1_PSU (R23.2 U5.1 U5.2)
VSWITCH: VESTE_V3.1_MCU (R16.2), VESTE_V3.1_PSU (8 pins)
ALIM_ONOFF: VESTE_V3.1_MCU (IC1.37 Q2.1), VESTE_V3.1_PSU (D9.4)
ALUM_PYRO: VESTE_V3.1_MCU (5 pins), VESTE_V3.1_PSU (J5.2 J6.2 R24.1)
CHARGE_STATUS: VESTE_V3.1_MCU (IC1.11), VESTE_V3.1_PSU (R9.1 R12.1)
DETECT_FIDLOCK: VESTE_V3.1_MCU (IC1.7 U2.C2), VESTE_V3.1_PSU (D9.6)
DETECT_SELLE: VESTE_V3.1_MCU (IC1.26 U2.A2), VESTE_V3.1_PSU (D7.1 IC7.3 R29.1)
DETECT_USB: VESTE_V3.1_MCU (IC1.12), VESTE_V3.1_PSU (IC8.8 R30.2)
